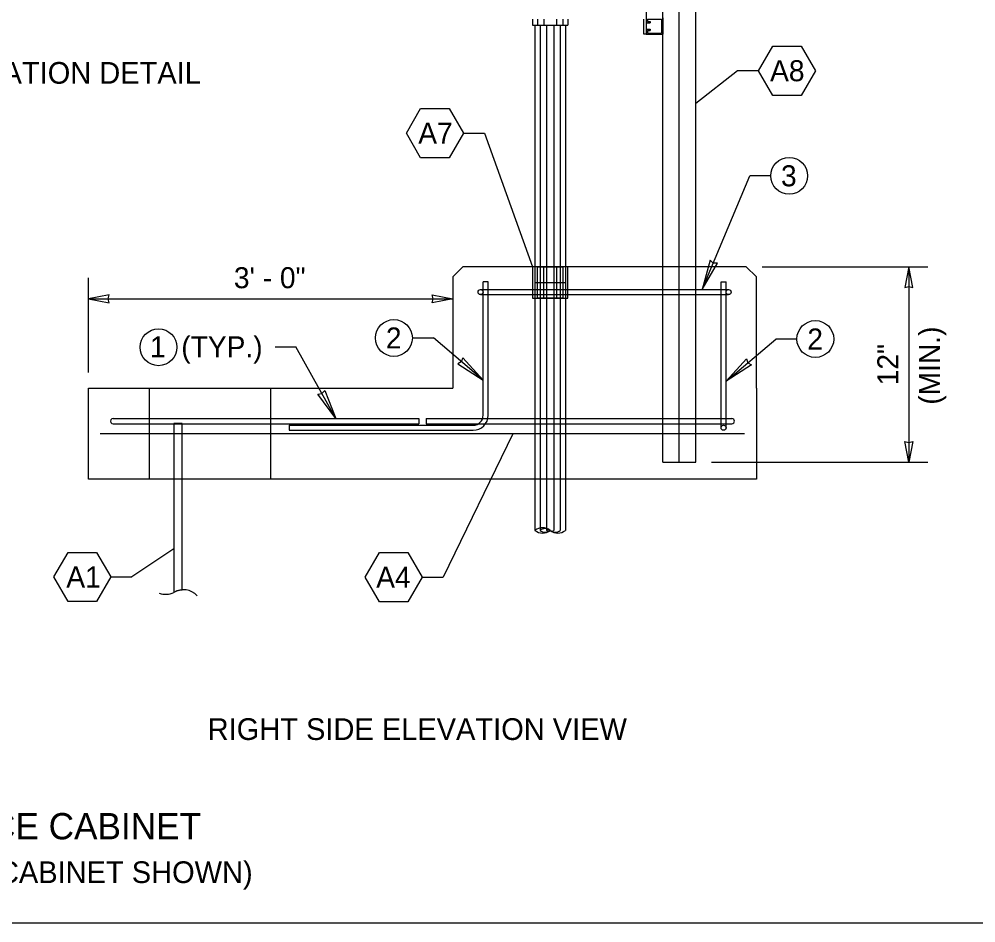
# Model space of a CAD drawing. Extents: x 99862 to 103151, y 100000 to 117076.
# Drawn here: x 100882 to 101609, y 103000 to 103687 of the extents above; entities that cross this region are included whole.
import ezdxf

# ---------------------------------------------------------------- set-up
doc = ezdxf.new("R2010")
doc.units = 0
for name, color, linetype in [('Default', 7, 'Continuous'), ('Level 1', 7, 'Continuous'), ('Level 11', 7, 'Continuous'), ('Level 15', 7, 'Continuous'), ('Level 20', 7, 'Continuous'), ('Level 40', 7, 'Continuous')]:
    doc.layers.add(name, color=color, linetype=linetype)

msp = doc.modelspace()

# ---------------------------------------------------------------- linework, layer by layer
at = {"layer": 'Default'}
for p, q in [((101234.61, 103385.74), (101234.61, 103487.06)), ((101238.46, 103487.06), (101234.61, 103487.06)), ((101238.46, 103385.74), (101238.46, 103487.06)), ((101415.45, 103376.12), (101415.45, 103487.06)), ((101415.45, 103487.06), (101419.29, 103487.06)), ((101419.29, 103376.12), (101419.29, 103487.06)), ((101232.69, 103481.29), (101421.22, 103481.29)), ((101232.69, 103477.44), (101421.22, 103477.44)), ((100953.18, 103383.06), (101185.72, 103383.06)), ((101185.72, 103383.06), (101185.72, 103379.22)), ((101191.17, 103383.06), (101191.17, 103379.22)), ((101191.17, 103383.06), (101423.71, 103383.06)), ((100953.18, 103379.22), (101185.72, 103379.22)), ((101087.04, 103378.05), (101226.92, 103378.05)), ((101087.04, 103378.05), (101087.04, 103374.2)), ((101087.04, 103374.2), (101226.92, 103374.2)), ((101191.17, 103379.22), (101423.71, 103379.22))]:
    msp.add_line(p, q, dxfattribs=at)
for centre in [(101232.69, 103479.36), (101421.22, 103479.36), (101417.37, 103376.12)]:
    msp.add_circle(centre, 1.92, dxfattribs=at)
for centre, radius, start, end in [((100953.18, 103381.14), 1.92, 90, 270.01001), ((101226.92, 103385.74), 11.54, 270, 0), ((101226.92, 103385.74), 7.7, 270, 0), ((101423.71, 103381.14), 1.92, 270, 90)]:
    msp.add_arc(centre, radius, start, end, dxfattribs=at)
at = {"layer": 'Level 1'}
for p, q in [((101272.08, 103686.95), (101272.08, 103682.42)), ((101275.92, 103686.95), (101275.92, 103682.42)), ((101280.73, 103686.95), (101280.73, 103682.42)), ((101290.35, 103686.95), (101290.35, 103682.42)), ((101295.16, 103686.95), (101295.16, 103682.42)), ((101299.01, 103686.95), (101299.01, 103682.42)), ((101272.08, 103682.42), (101299.01, 103682.42)), ((101274, 103682.42), (101274, 103498.41)), ((101275.92, 103682.42), (101295.16, 103682.42)), ((101277.85, 103682.42), (101277.85, 103498.41)), ((101280.73, 103682.42), (101290.35, 103682.42)), ((101282.66, 103682.42), (101282.66, 103498.41)), ((101288.43, 103682.42), (101288.43, 103498.41)), ((101293.24, 103682.42), (101293.24, 103498.41)), ((101297.09, 103682.42), (101297.09, 103498.41)), ((101274, 103498.41), (101274, 103298.01)), ((101277.85, 103498.41), (101277.85, 103298.01)), ((101282.66, 103498.41), (101282.66, 103298.01)), ((101288.43, 103498.41), (101288.43, 103298.01)), ((101293.24, 103498.41), (101293.24, 103298.01)), ((101297.09, 103498.41), (101297.09, 103298.01)), ((101274, 103486.49), (101297.09, 103486.49))]:
    msp.add_line(p, q, dxfattribs=at)
for points in [[(99862, 102999.5), (103151, 102999.5), (103151, 105075.5), (99862, 105075.5)], [(101272.08, 103474.57), (101299.01, 103474.57), (101299.01, 103498.41), (101272.08, 103498.41)], [(101295.16, 103474.57), (101275.92, 103474.57), (101275.92, 103498.41), (101295.16, 103498.41)], [(101280.73, 103498.41), (101290.35, 103498.41), (101290.35, 103474.57), (101280.73, 103474.57)], [(100999.46, 103379.42), (100999.46, 103250.95), (101001.65, 103252.05), (101003.66, 103252.59), (101005.67, 103252.93), (101005.72, 103379.42)]]:
    msp.add_lwpolyline(points, close=True, dxfattribs=at)
for centre, radius, start, end in [((101279.77, 103290.93), 9.14, 50.83294, 129.16706), ((101279.77, 103305.09), 9.14, 230.83294, 309.16706), ((101281.7, 103293.29), 6.09, 50.83294, 129.16706), ((101281.7, 103302.73), 6.09, 230.83294, 309.16706), ((101284.1, 103296.24), 2.28, 50.83294, 129.16706), ((101284.1, 103299.78), 2.28, 230.83294, 309.16706), ((101291.31, 103305.09), 9.14, 230.83294, 309.16706), ((101289.39, 103302.73), 6.09, 230.83294, 309.16706), ((101286.99, 103299.78), 2.28, 230.83294, 309.16706), ((100993.1, 103264.08), 14.61, 250.75714, 295.35062), ((101006.67, 103238.79), 14.13, 42.37775, 121.18132)]:
    msp.add_arc(centre, radius, start, end, dxfattribs=at)
at = {"layer": 'Level 11'}
for p, q in [((100980.68, 103406.26), (100980.68, 103337.01)), ((101073.02, 103406.26), (101073.02, 103337.01))]:
    msp.add_line(p, q, dxfattribs=at)
for points in [[(101219.22, 103498.6), (101211.53, 103490.91), (101211.53, 103406.26)], [(101434.68, 103498.6), (101219.22, 103498.6)], [(101442.38, 103406.26), (101442.38, 103490.91), (101434.68, 103498.6)], [(100934.51, 103406.26), (101211.53, 103406.26)], [(100934.51, 103337.01), (100934.51, 103406.26)], [(101442.38, 103406.26), (101442.38, 103337.01)], [(101442.38, 103337.01), (100934.51, 103337.01)]]:
    msp.add_lwpolyline(points, dxfattribs=at)
at = {"layer": 'Level 15'}
for p, q in [((101356.72, 103675.41), (101356.72, 103686.95)), ((101358.65, 103675.41), (101356.72, 103675.41)), ((101427.9, 103647.71), (101396.21, 103622.83)), ((101443.9, 103647.71), (101427.9, 103647.71)), ((101219.54, 103600.2), (101235.54, 103600.2)), ((101235.54, 103600.2), (101272.08, 103498.41)), ((101401.17, 103481.29), (101437.31, 103567.76)), ((101453.31, 103567.76), (101437.31, 103567.76)), ((101446.68, 103498.6), (101572.75, 103498.6)), ((101558.29, 103498.6), (101558.29, 103350.02)), ((100934.51, 103418.26), (100934.51, 103490.26)), ((100934.51, 103474.26), (101211.53, 103474.26)), ((101180.75, 103444.4), (101196.75, 103444.4)), ((101234.61, 103412.31), (101196.73, 103444.4)), ((101419.29, 103411.54), (101457.18, 103443.63)), ((101473.16, 103443.63), (101457.16, 103443.63)), ((101076.43, 103437.67), (101092.21, 103437.67)), ((101122.59, 103383.06), (101092.21, 103437.67)), ((101257.07, 103371.41), (101204.13, 103262.41)), ((101408.21, 103350.02), (101572.75, 103350.02)), ((100999.46, 103284.06), (100967.43, 103262.6)), ((100951.43, 103262.6), (100967.43, 103262.6)), ((101188.13, 103262.41), (101204.13, 103262.41))]:
    msp.add_line(p, q, dxfattribs=at)
for points in [[(101401.17, 103481.29), (101412.73, 103501.2), (101409.57, 103501.38), (101407.22, 103503.5)], [(101558.29, 103498.6), (101555.21, 103482.88), (101558.29, 103483.6), (101561.38, 103482.88)], [(100934.51, 103474.26), (100950.23, 103471.18), (100949.51, 103474.26), (100950.23, 103477.34)], [(101211.53, 103474.26), (101195.8, 103471.18), (101196.53, 103474.26), (101195.8, 103477.34)], [(101234.61, 103412.31), (101219.12, 103429.34), (101218, 103426.38), (101215.26, 103424.79)], [(101419.29, 103411.54), (101434.79, 103428.57), (101435.91, 103425.61), (101438.64, 103424.02)], [(101122.59, 103383.06), (101108.88, 103401.56), (101112, 103402.09), (101114.1, 103404.47)], [(101558.29, 103350.02), (101555.21, 103365.74), (101558.29, 103365.01), (101561.38, 103365.74)]]:
    msp.add_lwpolyline(points, close=True, dxfattribs=at)
at = {"layer": 'Level 20'}
for points in [[(101443.9, 103647.71), (101454.73, 103666.46), (101476.38, 103666.46), (101487.19, 103647.71), (101476.38, 103628.96), (101454.73, 103628.96), (101443.9, 103647.71)], [(101176.25, 103600.2), (101187.08, 103618.95), (101208.73, 103618.95), (101219.54, 103600.2), (101208.73, 103581.45), (101187.08, 103581.45), (101176.25, 103600.2)], [(100908.15, 103262.6), (100918.98, 103281.35), (100940.63, 103281.35), (100951.43, 103262.6), (100940.63, 103243.85), (100918.98, 103243.85), (100908.15, 103262.6)], [(101144.84, 103262.41), (101155.67, 103281.15), (101177.32, 103281.15), (101188.13, 103262.41), (101177.32, 103243.66), (101155.67, 103243.66), (101144.84, 103262.41)]]:
    msp.add_lwpolyline(points, dxfattribs=at)
for centre in [(101467.31, 103567.76), (101166.75, 103444.4), (101487.16, 103443.63), (100987.78, 103437.33)]:
    msp.add_circle(centre, 14, dxfattribs=at)
at = {"layer": 'Level 40'}
for p, q in [((101358.65, 104006.3), (101358.65, 103675.41)), ((101371.19, 103498.6), (101371.19, 104006.3)), ((101383.7, 103498.6), (101383.7, 104006.3)), ((101396.21, 103498.6), (101396.21, 104006.3)), ((101358.65, 103687.93), (101358.65, 103684.05)), ((101359.64, 103686.95), (101370.18, 103686.95)), ((101359.64, 103686.95), (101359.64, 103685.05)), ((101359.64, 103685.05), (101361.61, 103685.05)), ((101361.61, 103685.05), (101361.61, 103684.1)), ((101370.18, 103686.95), (101370.18, 103676.39)), ((101371.15, 103687.93), (101371.15, 103675.41)), ((101358.65, 103684.1), (101361.61, 103684.1)), ((101358.65, 103679.21), (101361.61, 103679.21)), ((101358.65, 103679.21), (101358.65, 103675.41)), ((101359.64, 103678.28), (101361.61, 103678.28)), ((101359.64, 103678.28), (101359.64, 103676.39)), ((101361.61, 103679.21), (101361.61, 103678.28)), ((101358.65, 103675.41), (101371.15, 103675.41)), ((101359.64, 103676.39), (101370.18, 103676.39)), ((101371.19, 103350.02), (101371.19, 103498.6)), ((101383.7, 103350.02), (101383.7, 103498.6)), ((101396.21, 103350.02), (101396.21, 103498.6)), ((100943.49, 103371.63), (101433.4, 103371.63)), ((101371.19, 103350.02), (101383.7, 103350.02)), ((101383.7, 103350.02), (101396.21, 103350.02))]:
    msp.add_line(p, q, dxfattribs=at)

# ---------------------------------------------------------------- texts
at = {"layer": 'Level 20'}
for s, height, p in [('A8', 16, (101452.77, 103639.71)), ('CODUIT TERMINATION DETAIL', 16.5, (100693.93, 103637.83)), ('A7', 16, (101185.27, 103592.2)), ('3', 16, (101461.04, 103559.77)), ('3\' - 0"', 16, (101045.08, 103482.26)), ('2', 16, (101160.64, 103436.41)), ('1  (TYP.)', 16, (100981.29, 103429.67)), ('2', 16, (101481.06, 103435.64)), ('A1', 16, (100917.68, 103254.6)), ('A4', 16, (101153.29, 103254.41)), ('RIGHT SIDE ELEVATION VIEW', 16.5, (101025.16, 103138.64)), ('STRUT MOUNT SERVICE CABINET', 20, (100577.34, 103063.05)), ('(TYPE B MODIFIED SERVICE CABINET SHOWN)', 16.5, (100556.74, 103029.8))]:
    msp.add_text(s, height=height, dxfattribs=at).set_placement(p)
for s, p in [('(MIN.)', (101581.94, 103393.68)), ('12"', (101550.29, 103408.44))]:
    msp.add_text(s, height=16, rotation=90, dxfattribs=at).set_placement(p)

doc.saveas('drawing.dxf')
